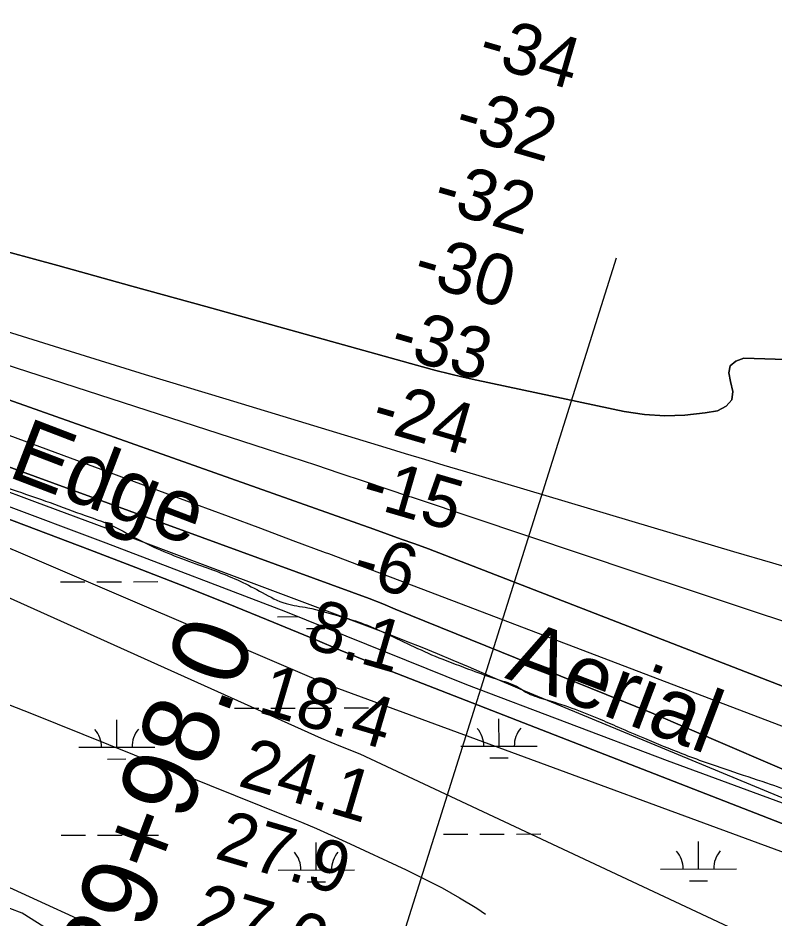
# Model space of a CAD drawing. Extents: x 3361039 to 3398939, y 576572 to 602007.
# Drawn here: x 3391844 to 3392837, y 584171 to 585353 of the extents above; entities that cross this region are included whole.
import ezdxf

# ---------------------------------------------------------------- set-up
doc = ezdxf.new("R2010")
doc.units = 0
for name, color, linetype in [('V-RIVR-EDGE', 7, 'Continuous'), ('V-RIVR-IDEN', 7, 'Continuous'), ('V-RIVR-RANG', 7, 'Continuous'), ('V-SITE-VEGE', 7, 'Continuous'), ('V-SURV-IDEN', 7, 'Continuous'), ('V-TOPO-DPTH', 7, 'Continuous'), ('V-TOPO-MAJR', 7, 'Continuous'), ('V-TOPO-MINR', 7, 'Continuous'), ('V-TOPO-WATR', 7, 'Continuous'), ('V-WETL-SWMP', 7, 'Continuous')]:
    doc.layers.add(name, color=color, linetype=linetype)

msp = doc.modelspace()

# ---------------------------------------------------------------- linework, layer by layer
at = {"layer": 'V-RIVR-EDGE'}
msp.add_spline([(3387368.6, 585771), (3387389, 585767.6), (3387407.3, 585766.1), (3387418.2, 585761.7), (3387425.5, 585756.5), (3387441.6, 585752.8), (3387452.6, 585751.4), (3387462.1, 585753.9), (3387477.4, 585758.2), (3387482.9, 585759.3), (3387491.7, 585759.3), (3387502.3, 585758.2), (3387510.3, 585756.3), (3387521.6, 585753), (3387530.1, 585752.3), (3387538.5, 585752.2), (3387549.8, 585752.2), (3387558.9, 585755.5), (3387571.4, 585756.9), (3387583.4, 585757.3), (3387598.4, 585756.1), (3387629.8, 585749.5), (3387659.8, 585743.5), (3387703.3, 585736.8), (3387727.4, 585734.2), (3387739.1, 585733.5), (3387750.8, 585734.2), (3387753.7, 585731.6), (3387763.2, 585723.9), (3387774.5, 585720.6), (3387790.6, 585719.8), (3387800.1, 585721.6), (3387814, 585720.1), (3387824.6, 585720.1), (3387847.3, 585714.2), (3387884.2, 585709.4), (3387930.2, 585702.7), (3387980.6, 585701.1), (3388035.1, 585696.5), (3388076, 585694.6), (3388096.9, 585693.8), (3388120.3, 585690.5), (3388145.1, 585685.3), (3388171.8, 585682.3), (3388198.8, 585676.8), (3388222.6, 585669.4), (3388245.6, 585660.6), (3388260.9, 585655.4), (3388279.6, 585655.4), (3388291.3, 585658.3), (3388298.9, 585663.7), (3388299.3, 585666.3), (3388299, 585670.7), (3388290.6, 585674.4), (3388291.7, 585677.3), (3388293.9, 585678.4), (3388303, 585677.6), (3388318.7, 585676.5), (3388334.1, 585672.8), (3388354.1, 585663.6), (3388357.1, 585659.9), (3388363.3, 585658.1), (3388368.4, 585658.1), (3388371, 585661), (3388375.3, 585662.1), (3388379, 585661.3), (3388383, 585659.1), (3388383.7, 585654.4), (3388384.1, 585649.3), (3388389.9, 585647.4), (3388406, 585642.3), (3388468.9, 585637.7), (3388491.5, 585635.8), (3388534.6, 585628.4), (3388578.1, 585619.2), (3388610.6, 585613.6), (3388635.9, 585612.1), (3388727.9, 585599.4), (3388768.5, 585591.7), (3388822.6, 585580.9), (3388865, 585570.6), (3388906.6, 585562.8), (3388924.1, 585559.5), (3388938.8, 585562), (3388961.4, 585563.4), (3388974.2, 585560.1), (3389007.5, 585553.4), (3389018.8, 585554.5), (3389027.2, 585555.9), (3389037.1, 585555.9), (3389051.7, 585553.7), (3389061.2, 585553.3), (3389081.3, 585552.1), (3389098.1, 585551), (3389120.4, 585548.7), (3389143.4, 585546.5), (3389160.2, 585542.1), (3389200.8, 585534.7), (3389222.3, 585525.1), (3389247.2, 585519.2), (3389280.4, 585509.6), (3389307.5, 585497.8), (3389334.5, 585487.2), (3389349.5, 585483.1), (3389361.5, 585483.1), (3389382.7, 585479), (3389397, 585476.8), (3389416.7, 585468.7), (3389441.9, 585458.4), (3389464.9, 585451.4), (3389479.5, 585449.2), (3389506.2, 585446.2), (3389533.2, 585447.2), (3389558.5, 585444.2), (3389577.8, 585437.9), (3389603.4, 585431.3), (3389618.7, 585425.1), (3389639.2, 585415.1), (3389657.8, 585410.3), (3389693.2, 585404.8), (3389768.9, 585383), (3389806.5, 585373), (3389854.3, 585362.3), (3389881.7, 585358.6), (3389913.9, 585354.5), (3389953.7, 585349.3), (3390008.2, 585341.8), (3390037.8, 585336.3), (3390074.3, 585327.8), (3390128, 585312.7), (3390164.5, 585301.6), (3390200.7, 585289.8), (3390292.7, 585255.6), (3390327.1, 585241.3), (3390360.7, 585231.7), (3390404.5, 585221), (3390454.9, 585214.3), (3390483.1, 585210.5), (3390491.8, 585209.4), (3390494.4, 585207.2), (3390501.3, 585201), (3390507.9, 585200.6), (3390527.3, 585196.2), (3390545.9, 585195), (3390557.6, 585194.3), (3390574.4, 585189.8), (3390605.5, 585179.5), (3390698.6, 585148.2), (3390763.2, 585126.9), (3390811.1, 585111), (3390852.4, 585097.8), (3390900.9, 585081.6), (3390948.1, 585063.5), (3390993.7, 585048.4), (3391036.8, 585031.9), (3391070.8, 585020.1), (3391140.5, 584997.6), (3391201.5, 584974.1), (3391247.5, 584957.5), (3391310.7, 584933.6), (3391362.2, 584914.8), (3391400.6, 584900.1), (3391441.8, 584885.7), (3391505.4, 584861.1), (3391563.5, 584841.9), (3391658.8, 584807.3), (3391712.8, 584786), (3391758.8, 584767.3), (3391796.1, 584749.6), (3391880.4, 584718.3), (3391926.8, 584701.4), (3391969.2, 584685.2), (3392003.9, 584666.9), (3392040, 584650.3), (3392077.6, 584636), (3392135.7, 584613.2), (3392164.9, 584598.1), (3392196, 584583.8), (3392224.8, 584578.2), (3392263.5, 584567.9), (3392290.6, 584559.8), (3392322.7, 584546.5), (3392396.5, 584512.7), (3392439.9, 584496.2), (3392471.7, 584484.8), (3392502, 584473.3), (3392510.8, 584467.5), (3392535.2, 584458.3), (3392606.1, 584432.9), (3392632.4, 584421.5), (3392666.7, 584406.8), (3392715.6, 584386.9), (3392777.4, 584364.8), (3392827, 584348.3), (3392863.6, 584335.4), (3392897.9, 584321.8), (3392928.6, 584307.8), (3392965.4, 584294.9), (3393010, 584279.1), (3393054.6, 584263.2), (3393092.5, 584248.5), (3393195.2, 584206.6), (3393234.2, 584187.9), (3393264.5, 584173.5), (3393294.1, 584162.1), (3393336.8, 584147.4), (3393374.5, 584136.3), (3393402.2, 584127.5), (3393414.3, 584119.8), (3393435.4, 584109.1), (3393459.2, 584098.1), (3393478.9, 584087.5), (3393513.6, 584076.4), (3393541.7, 584067.2), (3393588.1, 584047.4), (3393643.2, 584028.9), (3393668.4, 584018.3), (3393699.8, 584005), (3393737.1, 583991.8), (3393781.7, 583976), (3393884.7, 583943.2), (3393927, 583928.8), (3393981.1, 583908.2), (3394043.9, 583885.4), (3394095.8, 583868.1), (3394154.9, 583847.1), (3394200.2, 583830.5), (3394247, 583816.2), (3394293, 583801.4), (3394349.6, 583781.2), (3394409.1, 583754.7), (3394451.8, 583730.5), (3394470.5, 583720.2), (3394481.8, 583715.4), (3394494.2, 583713.6), (3394502.6, 583708.1), (3394507.3, 583700.4), (3394511.3, 583697.8), (3394522.7, 583692.3), (3394557.3, 583675.8), (3394600.4, 583659.9), (3394658.1, 583638.9), (3394704.5, 583623.5), (3394760.4, 583607.6), (3394824, 583588.8), (3394867.8, 583570.8), (3394925.9, 583546.9), (3394972.2, 583528.9), (3394995.6, 583520), (3395064.7, 583504.2), (3395088.4, 583499.3), (3395120.2, 583491.6), (3395149.1, 583480.5), (3395173.2, 583476.8), (3395201.3, 583471.3), (3395236.4, 583459.9), (3395256.8, 583451.8), (3395280.9, 583445.5), (3395300.3, 583445.1), (3395316.7, 583440.7), (3395324.4, 583433.3), (3395335.3, 583426), (3395353.6, 583417.9), (3395398.9, 583403.9), (3395426.3, 583397.2), (3395442, 583391), (3395455.9, 583383.3), (3395476, 583377.8), (3395495.7, 583369.3), (3395511, 583368.2), (3395530.4, 583365.9), (3395550.5, 583361.8), (3395654.6, 583334.9), (3395704.7, 583322.4), (3395743.7, 583306.9), (3395765.3, 583295.5), (3395788.3, 583286.3), (3395816.4, 583278.9), (3395861.7, 583270.8), (3395916.2, 583261.5), (3395960.7, 583252.6), (3396008.6, 583242.6), (3396060.8, 583230.5), (3396093.4, 583222.3), (3396135.4, 583208.7), (3396170.1, 583199.8), (3396204.4, 583191.3), (3396254.8, 583177.3), (3396301.2, 583165.9), (3396364.4, 583152.9), (3396399.1, 583144.4), (3396426.9, 583138.5), (3396463.1, 583133), (3396489.8, 583132.9), (3396523.4, 583130.2), (3396607.8, 583114), (3396670.3, 583102.1), (3396708.3, 583095.4), (3396743, 583089.5), (3396775.1, 583083.9)], degree=3, dxfattribs=at)
at = {"layer": 'V-RIVR-RANG'}
msp.add_line((3392269.3, 583893), (3392629.9, 585037.5), dxfattribs=at)
at = {"layer": 'V-SITE-VEGE'}
for p, q in [((3391762.8, 584736.9), (3391959.5, 584663.6)), ((3391959.5, 584663.6), (3392195.2, 584573.3)), ((3392195.2, 584573.3), (3392433.1, 584477.5)), ((3392433.1, 584477.5), (3392696.5, 584377.7)), ((3392696.5, 584377.7), (3393110.5, 584224.5)), ((3392021, 584124.8), (3391693.3, 584274.3))]:
    msp.add_line(p, q, dxfattribs=at)
at = {"layer": 'V-TOPO-DPTH'}
for points in [[(3390678.7, 585282.1), (3390852.2, 585234.7), (3390949.9, 585207.6), (3391047.4, 585179.9), (3391144.7, 585151.5), (3391241.8, 585122.5), (3391423.6, 585067.6), (3391453.4, 585058.5), (3391483.2, 585049.4), (3391513, 585040.1), (3391542.7, 585030.8), (3391694.3, 584983.1), (3391799.9, 584950), (3391905.5, 584917.2), (3392011.2, 584884.7), (3392117, 584852.4), (3392327.2, 584788.6), (3392352.5, 584780.9), (3392377.9, 584773.2), (3392403.2, 584765.6), (3392428.6, 584758.1), (3392783.6, 584652.3), (3392834.9, 584637), (3392886.4, 584621.7)], [(3390678.7, 585282.1), (3390852.2, 585234.7), (3390949.9, 585207.6), (3391047.4, 585179.9), (3391144.7, 585151.5), (3391241.8, 585122.5), (3391423.6, 585067.6), (3391453.4, 585058.5), (3391483.2, 585049.4), (3391513, 585040.1), (3391542.7, 585030.8), (3391694.3, 584983.1), (3391799.9, 584950), (3391905.5, 584917.2), (3392011.2, 584884.7), (3392117, 584852.4), (3392327.2, 584788.6), (3392352.5, 584780.9), (3392377.9, 584773.2), (3392403.2, 584765.6), (3392428.6, 584758.1), (3392783.6, 584652.3), (3392834.9, 584637), (3392886.4, 584621.7)], [(3393031.5, 584404.1), (3392383, 584655.6), (3392365.1, 584662), (3392347.2, 584668.5), (3392329.2, 584674.9), (3392311.3, 584681.3), (3391705.7, 584895.7), (3391665.3, 584910.1), (3391624.9, 584924.5), (3391584.6, 584939.1), (3391544.3, 584953.7), (3391492.3, 584972.7), (3391478, 584977.8), (3391463.6, 584982.9), (3391449.2, 584987.9), (3391434.8, 584992.8), (3391420.3, 584997.6), (3391405.8, 585002.3), (3391391.2, 585006.9), (3391376.6, 585011.3), (3390699.4, 585214.1), (3390668.7, 585223.2)], [(3390668.7, 585223.2), (3390699.4, 585214.1), (3391376.6, 585011.3), (3391391.2, 585006.9), (3391405.8, 585002.3), (3391420.3, 584997.6), (3391434.8, 584992.8), (3391449.2, 584987.9), (3391463.6, 584982.9), (3391478, 584977.8), (3391492.3, 584972.7), (3391544.3, 584953.7), (3391584.6, 584939.1), (3391624.9, 584924.5), (3391665.3, 584910.1), (3391705.7, 584895.7), (3392311.3, 584681.3), (3392329.2, 584674.9), (3392347.2, 584668.5), (3392365.1, 584662), (3392383, 584655.6), (3393031.5, 584404.1)], [(3392928.6, 584331.6), (3392676, 584440.3), (3392339.2, 584576.6), (3392323.1, 584583.4), (3392305.2, 584590.3), (3391596.6, 584849.1), (3391504.7, 584888.5), (3391448.6, 584913.4), (3391429.9, 584921.1), (3391160.2, 585008.6), (3390745.1, 585150.1), (3390651.5, 585182.7)], [(3390651.5, 585182.7), (3390745.1, 585150.1), (3391160.2, 585008.6), (3391429.9, 584921.1), (3391448.6, 584913.4), (3391504.7, 584888.5), (3391596.6, 584849.1), (3392305.2, 584590.3), (3392323.1, 584583.4), (3392339.2, 584576.6), (3392676, 584440.3), (3392928.6, 584331.6)], [(3392986.7, 584240.6), (3392333.6, 584495.2), (3392300.5, 584509), (3392267.3, 584522.7), (3392234.1, 584536.4), (3392180.2, 584558.7), (3392119.9, 584583.3), (3392059.6, 584607.5), (3391998.9, 584631.1), (3391938.2, 584654.4), (3391473.7, 584830.1), (3391448.8, 584839.4), (3391423.9, 584848.6), (3391399, 584857.6), (3391374, 584866.5), (3391251.3, 584909.9), (3391164.7, 584940.1), (3391078.1, 584969.8), (3390991.1, 584998.8), (3390904, 585027.3), (3390649.8, 585109.3)], [(3393003.7, 584899.3), (3392797.3, 584906), (3392786.4, 584902), (3392779.2, 584895.9), (3392777.6, 584886.6), (3392779.7, 584875.1), (3392782.6, 584862.3), (3392781.4, 584851.3), (3392774, 584843.1), (3392762.5, 584836.7), (3392746.5, 584834), (3392719.8, 584831), (3392693.2, 584830), (3392666.6, 584832.1), (3392640.1, 584836.1), (3392446.5, 584877), (3392428.5, 584881), (3392410.6, 584885.2), (3392392.8, 584889.7), (3392375, 584894.5), (3392090.6, 584973.7), (3391993.6, 585000.6), (3391896.5, 585027.4), (3391799.4, 585053.9)], [(3391799.4, 585053.9), (3391896.5, 585027.4), (3391993.6, 585000.6), (3392090.6, 584973.7), (3392375, 584894.5), (3392392.8, 584889.7), (3392410.6, 584885.2), (3392428.5, 584881), (3392446.5, 584877), (3392640.1, 584836.1), (3392666.6, 584832.1), (3392693.2, 584830), (3392719.8, 584831), (3392746.5, 584834), (3392762.5, 584836.7), (3392774, 584843.1), (3392781.4, 584851.3), (3392782.6, 584862.3), (3392779.7, 584875.1), (3392777.6, 584886.6), (3392779.2, 584895.9), (3392786.4, 584902), (3392797.3, 584906), (3393003.7, 584899.3)]]:
    msp.add_lwpolyline(points, dxfattribs=at)
at = {"layer": 'V-TOPO-MAJR'}
msp.add_lwpolyline([(3391240.6, 584650.9), (3391340.5, 584626.7), (3391348.9, 584624.6), (3391357.2, 584622.3), (3391365.4, 584619.7), (3391373.6, 584617), (3391526.6, 584564.4), (3391611, 584534.6), (3391695.1, 584504), (3391778.7, 584472), (3391862, 584439.3), (3392196.6, 584304.7), (3392216.2, 584296.6), (3392235.8, 584288.3), (3392255.1, 584279.7), (3392274.4, 584270.9), (3392353.6, 584234), (3392377.4, 584222.4), (3392400.8, 584210.3), (3392423.8, 584197.3), (3392446.5, 584183.8), (3392458.1, 584176.1)], dxfattribs=at)
at = {"layer": 'V-TOPO-MINR'}
for points in [[(3390678.7, 585282.1), (3390852.2, 585234.7), (3390949.9, 585207.6), (3391047.4, 585179.9), (3391144.7, 585151.5), (3391241.8, 585122.5), (3391423.6, 585067.6), (3391453.4, 585058.5), (3391483.2, 585049.4), (3391513, 585040.1), (3391542.7, 585030.8), (3391694.3, 584983.1), (3391799.9, 584950), (3391905.5, 584917.2), (3392011.2, 584884.7), (3392117, 584852.4), (3392327.2, 584788.6), (3392352.5, 584780.9), (3392377.9, 584773.2), (3392403.2, 584765.6), (3392428.6, 584758.1), (3392783.6, 584652.3), (3392834.9, 584637), (3392886.4, 584621.7)], [(3390656, 585264.9), (3391449.4, 585020), (3391460.9, 585016.4), (3391472.4, 585012.8), (3391483.9, 585009.1), (3391495.4, 585005.4), (3392170, 584786.8), (3392202.3, 584776.3), (3392234.5, 584765.7), (3392266.6, 584755.1), (3392298.8, 584744.3), (3392358, 584724.5), (3392360.5, 584723.7), (3392363.1, 584722.8), (3392365.6, 584722), (3392368.2, 584721.1), (3392655.4, 584625), (3392725.2, 584601.8), (3392795, 584578.6), (3392864.8, 584555.5)], [(3390668.7, 585223.2), (3390699.4, 585214.1), (3391376.6, 585011.3), (3391391.2, 585006.9), (3391405.8, 585002.3), (3391420.3, 584997.6), (3391434.8, 584992.8), (3391449.2, 584987.9), (3391463.6, 584982.9), (3391478, 584977.8), (3391492.3, 584972.7), (3391544.3, 584953.7), (3391584.6, 584939.1), (3391624.9, 584924.5), (3391665.3, 584910.1), (3391705.7, 584895.7), (3392311.3, 584681.3), (3392329.2, 584674.9), (3392347.2, 584668.5), (3392365.1, 584662), (3392383, 584655.6), (3393031.5, 584404.1)], [(3390668.5, 585198), (3390896, 585128.7), (3390989.3, 585099.8), (3391082.4, 585070.2), (3391175.2, 585039.7), (3391267.7, 585008.5), (3391401.9, 584962.5), (3391427.1, 584953.7), (3391452.4, 584944.9), (3391477.5, 584935.8), (3391502.7, 584926.6), (3392077.3, 584714.2), (3392119.9, 584698.4), (3392162.5, 584682.6), (3392205.1, 584666.7), (3392247.6, 584650.9), (3392251.7, 584649.3), (3392292.2, 584634.1), (3392332.6, 584618.9), (3392373, 584603.5), (3392413.4, 584588.1), (3393024.8, 584355.3)], [(3390649.8, 585109.3), (3390904, 585027.3), (3390991.1, 584998.8), (3391078.1, 584969.8), (3391164.7, 584940.1), (3391251.3, 584909.9), (3391374, 584866.5), (3391399, 584857.6), (3391423.9, 584848.6), (3391448.8, 584839.4), (3391473.7, 584830.1), (3391938.2, 584654.4), (3391998.9, 584631.1), (3392059.6, 584607.5), (3392119.9, 584583.3), (3392180.2, 584558.7), (3392234.1, 584536.4), (3392267.3, 584522.7), (3392300.5, 584509), (3392333.6, 584495.2), (3392986.7, 584240.6)], [(3390617.2, 585092.9), (3390711.5, 585062.5), (3390770.4, 585043.3), (3390829.2, 585023.9), (3390887.9, 585004), (3390946.5, 584983.9), (3391393, 584829), (3391404.4, 584825), (3391415.8, 584821), (3391427.2, 584816.8), (3391438.5, 584812.5), (3391558.5, 584767), (3391629.6, 584739.5), (3391700.5, 584711.4), (3391771, 584682.4), (3391841.3, 584652.9), (3392226.2, 584488.1), (3392256.5, 584475.3), (3393034.3, 584188.9)], [(3390612.8, 585063.4), (3391305.1, 584824.7), (3391322, 584818.7), (3391338.9, 584812.3), (3391355.5, 584805.7), (3391372.1, 584798.7), (3391388.5, 584791.4), (3391404.9, 584784), (3391421.1, 584776.3), (3392242.1, 584407), (3392267.6, 584396.7), (3392293, 584386.4), (3392910, 584097.1)], [(3391799.4, 585053.9), (3391896.5, 585027.4), (3391993.6, 585000.6), (3392090.6, 584973.7), (3392375, 584894.5), (3392392.8, 584889.7), (3392410.6, 584885.2), (3392428.5, 584881), (3392446.5, 584877), (3392640.1, 584836.1), (3392666.6, 584832.1), (3392693.2, 584830), (3392719.8, 584831), (3392746.5, 584834), (3392762.5, 584836.7), (3392774, 584843.1), (3392781.4, 584851.3), (3392782.6, 584862.3), (3392779.7, 584875.1), (3392777.6, 584886.6), (3392779.2, 584895.9), (3392786.4, 584902), (3392797.3, 584906), (3393003.7, 584899.3)], [(3391757.7, 584758.2), (3391865.9, 584717.8), (3391974.1, 584677.3), (3392082.3, 584636.8), (3392298.4, 584555.9), (3392305.5, 584553.3), (3392312.6, 584550.6), (3392319.7, 584547.8), (3392326.8, 584545.1), (3392353.7, 584534.5), (3392374.2, 584526.4), (3392394.6, 584518.1), (3392414.9, 584509.6), (3392435.2, 584500.9), (3392467, 584487.2), (3392503.1, 584471.7), (3392936.5, 584291.9)]]:
    msp.add_lwpolyline(points, dxfattribs=at)
at = {"layer": 'V-TOPO-WATR'}
msp.add_lwpolyline([(3392928.6, 584331.6), (3392676, 584440.3), (3392339.2, 584576.6), (3392323.1, 584583.4), (3392305.2, 584590.3), (3391596.6, 584849.1), (3391504.7, 584888.5), (3391448.6, 584913.4), (3391429.9, 584921.1), (3391160.2, 585008.6), (3390745.1, 585150.1), (3390651.5, 585182.7)], dxfattribs=at)
at = {"layer": 'V-WETL-SWMP'}
for p, q in [((3391762.8, 584736.9), (3391959.5, 584663.6)), ((3391959.5, 584663.6), (3392195.2, 584573.3)), ((3391899.8, 584612.1), (3391931.8, 584612.2)), ((3391947.8, 584612.3), (3391979.8, 584612.3)), ((3391995.8, 584612.4), (3392027.8, 584612.5)), ((3392184.7, 584566.5), (3392212, 584566.6)), ((3392195.2, 584573.3), (3392433.1, 584477.5)), ((3392222.8, 584551.2), (3392246.8, 584551.2)), ((3392433.1, 584477.5), (3392696.5, 584377.7)), ((3392128.2, 584446.3), (3392160.2, 584446.3)), ((3392176.2, 584446.4), (3392208.2, 584446.5)), ((3392224.2, 584446.5), (3392256.2, 584446.6)), ((3392272.2, 584446.7), (3392304.2, 584446.7)), ((3391973.8, 584395.1), (3391973.7, 584431.1)), ((3392475.7, 584396.5), (3392475.6, 584432.5)), ((3391923.8, 584395), (3392023.8, 584395.2)), ((3392425.7, 584396.3), (3392525.7, 584396.6)), ((3391961.8, 584379.6), (3391985.8, 584379.7)), ((3392463.7, 584381), (3392487.7, 584381.1)), ((3392696.5, 584377.7), (3393110.5, 584224.5)), ((3391900.7, 584279.5), (3391932.7, 584279.6)), ((3391948.7, 584279.6), (3391980.7, 584279.7)), ((3391996.7, 584279.7), (3392028.7, 584279.8)), ((3392402.6, 584280.9), (3392434.6, 584280.9)), ((3392450.6, 584281), (3392482.6, 584281.1)), ((3392498.6, 584281.1), (3392530.6, 584281.2)), ((3392737.6, 584235.3), (3392737.5, 584271.3)), ((3392235.7, 584234), (3392235.6, 584270)), ((3392185.7, 584233.8), (3392285.7, 584234.1)), ((3392687.6, 584235.2), (3392787.6, 584235.5)), ((3392223.7, 584218.5), (3392247.7, 584218.6)), ((3392725.6, 584219.9), (3392749.6, 584219.9)), ((3391849.7, 584177.2), (3391774.7, 584205.1)), ((3391877.9, 584159.5), (3391849.7, 584177.2))]:
    msp.add_line(p, q, dxfattribs=at)
for centre, start, end in [((3391918.5, 584395.4), 359.3865, 40.9302), ((3392029, 584395.7), 139.3865, 180.9301), ((3392420.5, 584396.8), 359.3865, 40.9302), ((3392530.9, 584397.1), 139.3865, 180.9301), ((3392180.4, 584234.3), 359.3865, 40.9302), ((3392290.9, 584234.6), 139.3865, 180.9301), ((3392682.3, 584235.7), 359.3865, 40.9302), ((3392792.8, 584236), 139.3865, 180.9301)]:
    msp.add_arc(centre, 35.2, start, end, dxfattribs=at)

# ---------------------------------------------------------------- texts
at = {"layer": 'V-RIVR-IDEN'}
for s, rotation, p in [('Water Edge', 339.05, (3391523.5, 584867.9)), ('Aerial ', 339.2309, (3392482.1, 584486.4))]:
    msp.add_text(s, height=83, rotation=rotation, dxfattribs=at).set_placement(p)
at = {"layer": 'V-RIVR-RANG'}
for s, rotation, p in [('-34', 343.8157, (3392445.4, 585294.4)), ('-32', 343.8157, (3392414.5, 585199.3)), ('-32', 343.8157, (3392386.4, 585103.3)), ('-30', 343.8157, (3392360.1, 585006.8)), ('-33', 343.8157, (3392329.7, 584911.5)), ('-24', 343.8157, (3392305.4, 584814.4)), ('-15', 343.8157, (3392291.7, 584714.3)), ('-6', 343.8157, (3392279.8, 584613.6)), ('8.1', 343.8157, (3392219.3, 584527)), ('18.4', 343.5283, (3392157, 584441.6)), ('24.1', 343.5283, (3392131.1, 584345)), ('27.9', 343.5283, (3392100.5, 584249.8)), ('27.6', 343.5283, (3392070.9, 584154.2))]:
    msp.add_text(s, height=67, rotation=rotation, dxfattribs=at).set_placement(p)
at = {"layer": 'V-SURV-IDEN'}
msp.add_text('29+98.0', height=100, rotation=69.4766, dxfattribs=at).set_placement((3391986.1, 584082.9))

doc.saveas('drawing.dxf')
